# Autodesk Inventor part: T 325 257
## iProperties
Company: Mayer & Müller AG Schaltgeräte
Created: 2006-04
Part Number: T 325 257
Material: Standard
Document SubType Name: Modeling
Designer: I.Baliuc
Description: Schutzabdeckung, rechts
Density: 1 g/cm^3
Zweck: Vorkontakt HSLT
Author: T.Messerschmitt
Revision Number: 325257
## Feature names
1. Extrusion2
2. Rundung3 [Fillet]
3. Wandstärke1
4. Extrusion3
5. Bohrung1 [Hole]
